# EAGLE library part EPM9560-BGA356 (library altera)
EPM9560 MAX 9000 family
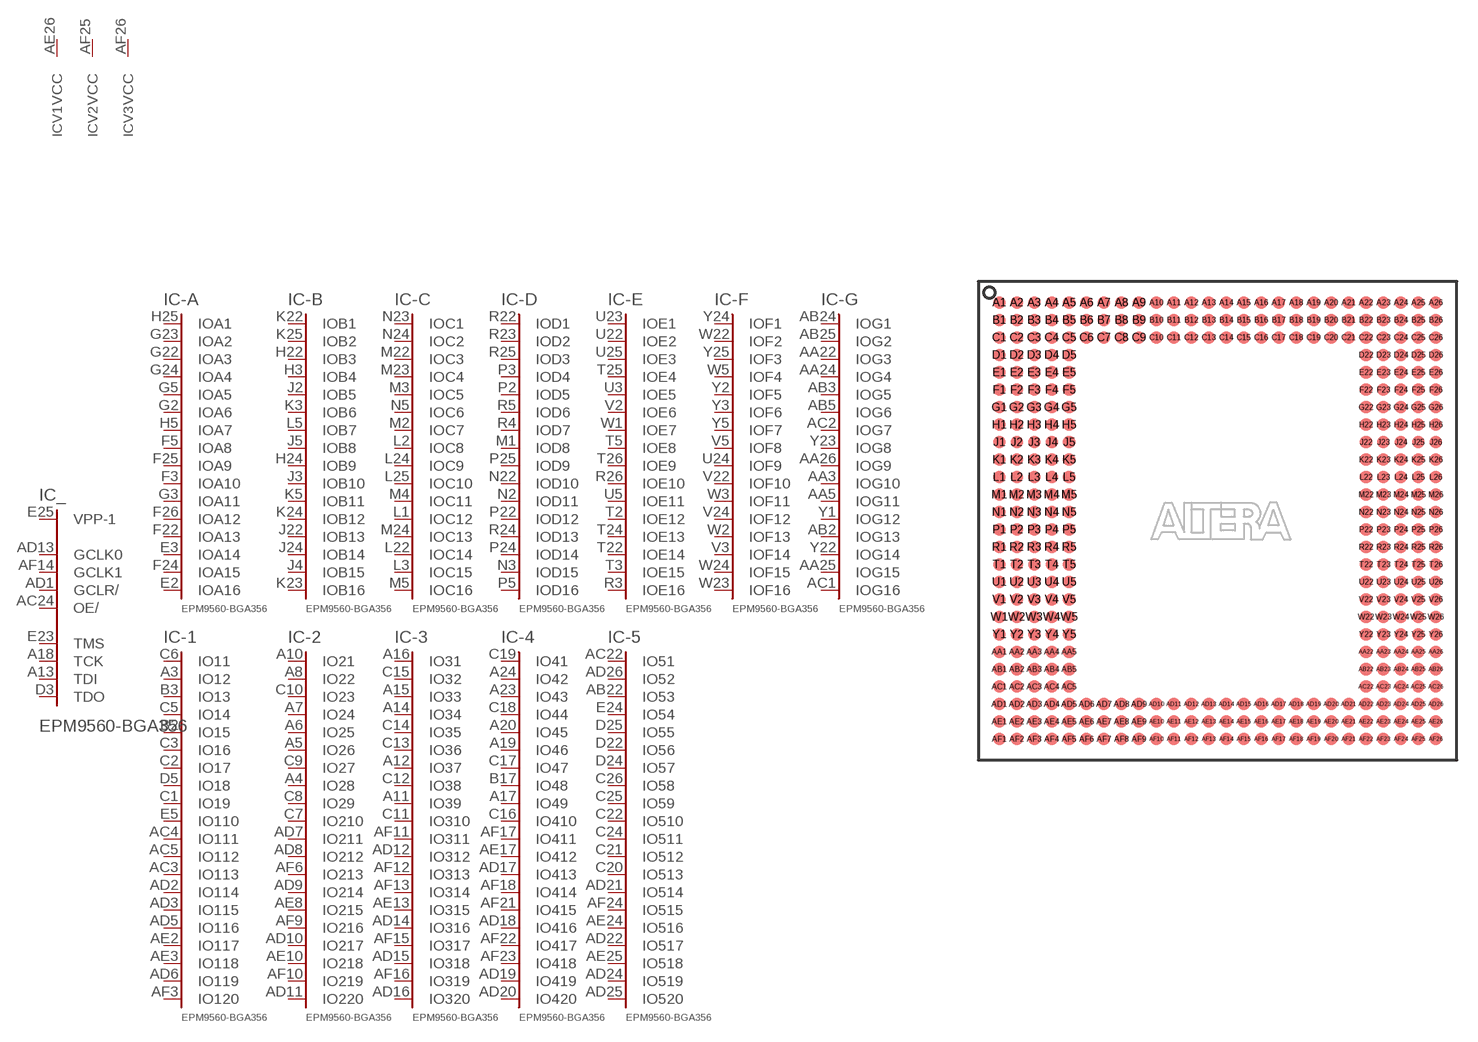
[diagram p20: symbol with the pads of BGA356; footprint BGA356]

Designator prefix IC; gates _=9560C356 -A=A16-0 -B=B16-0 -C=C16-0 -D=D16-0 -E=E16-0 -1=IO120 -2=IO220 -3=IO320 -4=IO420 -5=IO520 -F=F16-0 -G=G16-0 V1=VCCINT V2=VCCINT V3=VCCINT V4=VCCINT V5=VCCINT V6=VCCINT V7=VCCINT V8=VCCINT V9=VCCINT V10=VCCINT V11=VCCINT VO1=VCCIO VO2=VCCIO VO3=VCCIO VO4=VCCIO VO5=VCCIO VO6=VCCIO VO7=VCCIO VO8=VCCIO VO9=VCCIO VO10=VCCIO VO11=VCCIO VO12=VCCIO VO13=VCCIO VO14=VCCIO VO15=VCCIO VO16=VCCIO VO17=VCCIO G1=GND G2=GND G3=GND G4=GND G5=GND G6=GND G7=GND G8=GND G9=GND G10=GND G11=GND G12=GND G13=GND G14=GND G15=GND G16=GND G17=GND G18=GND G19=GND G20=GND G21=GND G22=GND G23=GND G24=GND G25=GND G26=GND G27=GND G28=GND G29=GND G30=GND G31=GND G32=GND G33=GND G34=GND G35=GND G36=GND G37=GND G38=GND G39=GND G40=GND G41=GND NC1=NC NC2=NC NC3=NC NC4=NC NC5=NC NC6=NC NC7=NC NC8=NC NC9=NC NC10=NC NC11=NC NC12=NC NC13=NC NC14=NC NC15=NC NC16=NC NC17=NC NC18=NC NC19=NC NC20=NC NC21=NC NC22=NC NC23=NC NC24=NC NC25=NC NC26=NC NC27=NC NC28=NC NC29=NC NC30=NC NC31=NC NC32=NC NC33=NC NC34=NC NC35=NC NC36=NC NC37=NC NC38=NC NC39=NC NC40=NC NC41=NC NC42=NC NC43=NC NC44=NC NC45=NC NC46=NC NC47=NC NC48=NC NC49=NC NC50=NC NC51=NC NC52=NC NC53=NC NC54=NC NC55=NC NC56=NC NC57=NC NC58=NC NC59=NC NC60=NC NC61=NC NC62=NC NC63=NC NC64=NC NC65=NC NC66=NC

## EPM9560-BGA356 (MPN: EPM9560ABC356-10; OC_FARNELL: unknown; OC_NEWARK: 51R9960)  [BGA356]
A1  VO6:VCCIO  pwr
A2  VO7:VCCIO  pwr
A3  -1:IO12
A4  -2:IO28
A5  -2:IO26
A6  -2:IO25
A7  -2:IO24
A8  -2:IO22
A9  G11:GND  pwr
A10  -2:IO21
A11  -3:IO39
A12  -3:IO37
A13  _:TDI
A14  -3:IO34
A15  -3:IO33
A16  -3:IO31
A17  -4:IO49
A18  _:TCK
A19  -4:IO46
A20  -4:IO45
A21  VO8:VCCIO  pwr
A22  G12:GND  pwr
A23  -4:IO43
A24  -4:IO42
A25  G13:GND  pwr
A26  G14:GND  pwr
AA1  VO1:VCCIO  pwr
AA2  G1:GND  pwr
AA3  -G:IOG10
AA4  NC1:NC  nc
AA5  -G:IOG11
AA22  -G:IOG3
AA23  NC2:NC  nc
AA24  -G:IOG4
AA25  -G:IOG15
AA26  -G:IOG9
AB1  G2:GND  pwr
AB2  -G:IOG13
AB3  -G:IOG5
AB4  NC3:NC  nc
AB5  -G:IOG6
AB22  -5:IO53
AB23  NC4:NC  nc
AB24  -G:IOG1
AB25  -G:IOG2
AB26  G3:GND  pwr
AC1  -G:IOG16
AC2  -G:IOG7
AC3  -1:IO113
AC4  -1:IO111
AC5  -1:IO112
AC22  -5:IO51
AC23  NC5:NC  nc
AC24  _:OE/  in
AC25  VO2:VCCIO  pwr
AC26  G4:GND  pwr
AD1  _:GCLR/  in
AD2  -1:IO114
AD3  -1:IO115
AD4  NC6:NC  nc
AD5  -1:IO116
AD6  -1:IO119
AD7  -2:IO211
AD8  -2:IO212
AD9  -2:IO214
AD10  -2:IO217
AD11  -2:IO220
AD12  -3:IO312
AD13  _:GCLK0  in
AD14  -3:IO316
AD15  -3:IO318
AD16  -3:IO320
AD17  -4:IO413
AD18  -4:IO416
AD19  -4:IO419
AD20  -4:IO420
AD21  -5:IO514
AD22  -5:IO517
AD23  NC7:NC  nc
AD24  -5:IO519
AD25  -5:IO520
AD26  -5:IO52
AE1  G5:GND  pwr
AE2  -1:IO117
AE3  -1:IO118
AE4  NC8:NC  nc
AE5  NC9:NC  nc
AE6  NC10:NC  nc
AE7  NC11:NC  nc
AE8  -2:IO215
AE9  NC12:NC  nc
AE10  -2:IO218
AE11  NC13:NC  nc
AE12  NC14:NC  nc
AE13  -3:IO315
AE14  NC15:NC  nc
AE15  NC16:NC  nc
AE16  NC17:NC  nc
AE17  -4:IO412
AE18  NC18:NC  nc
AE19  NC19:NC  nc
AE20  NC20:NC  nc
AE21  NC21:NC  nc
AE22  NC22:NC  nc
AE23  NC23:NC  nc
AE24  -5:IO516
AE25  -5:IO518
AE26  V1:VCC  pwr
AF1  G6:GND  pwr
AF2  G7:GND  pwr
AF3  -1:IO120
AF4  G8:GND  pwr
AF5  VO3:VCCIO  pwr
AF6  -2:IO213
AF7  G9:GND  pwr
AF8  VO4:VCCIO  pwr
AF9  -2:IO216
AF10  -2:IO219
AF11  -3:IO311
AF12  -3:IO313
AF13  -3:IO314
AF14  _:GCLK1  in
AF15  -3:IO317
AF16  -3:IO319
AF17  -4:IO411
AF18  -4:IO414
AF19  VO5:VCCIO  pwr
AF20  G10:GND  pwr
AF21  -4:IO415
AF22  -4:IO417
AF23  -4:IO418
AF24  -5:IO515
AF25  V2:VCC  pwr
AF26  V3:VCC  pwr
B1  VO9:VCCIO  pwr
B2  -1:IO15
B3  -1:IO13
B4  NC24:NC  nc
B5  NC25:NC  nc
B6  NC26:NC  nc
B7  NC27:NC  nc
B8  NC28:NC  nc
B9  NC29:NC  nc
B10  VO10:VCCIO  pwr
B11  NC30:NC  nc
B12  NC31:NC  nc
B13  NC32:NC  nc
B14  NC33:NC  nc
B15  NC34:NC  nc
B16  NC35:NC  nc
B17  -4:IO48
B18  NC36:NC  nc
B19  NC37:NC  nc
B20  NC38:NC  nc
B21  NC39:NC  nc
B22  NC40:NC  nc
B23  NC41:NC  nc
B24  VO11:VCCIO  pwr
B25  G15:GND  pwr
B26  G16:GND  pwr
C1  -1:IO19
C2  -1:IO17
C3  -1:IO16
C4  NC42:NC  nc
C5  -1:IO14
C6  -1:IO11
C7  -2:IO210
C8  -2:IO29
C9  -2:IO27
C10  -2:IO23
C11  -3:IO310
C12  -3:IO38
C13  -3:IO36
C14  -3:IO35
C15  -3:IO32
C16  -4:IO410
C17  -4:IO47
C18  -4:IO44
C19  -4:IO41
C20  -5:IO513
C21  -5:IO512
C22  -5:IO510
C23  NC43:NC  nc
C24  -5:IO511
C25  -5:IO59
C26  -5:IO58
D1  VO12:VCCIO  pwr
D2  G17:GND  pwr
D3  _:TDO
D4  NC44:NC  nc
D5  -1:IO18
D22  -5:IO56
D23  NC45:NC  nc
D24  -5:IO57
D25  -5:IO55
D26  V4:VCC  pwr
E1  G18:GND  pwr
E2  -A:IOA16
E3  -A:IOA14
E4  NC46:NC  nc
E5  -1:IO110
E22  NC47:NC  nc
E23  _:TMS
E24  -5:IO54
E25  _:VPP-1  in
E26  G19:GND  pwr
F1  V5:VCC  pwr
F2  G20:GND  pwr
F3  -A:IOA10
F4  NC48:NC  nc
F5  -A:IOA8
F22  -A:IOA13
F23  NC49:NC  nc
F24  -A:IOA15
F25  -A:IOA9
F26  -A:IOA12
G1  G21:GND  pwr
G2  -A:IOA6
G3  -A:IOA11
G4  NC50:NC  nc
G5  -A:IOA5
G22  -A:IOA3
G23  -A:IOA2
G24  -A:IOA4
G25  G22:GND  pwr
G26  G23:GND  pwr
H1  V6:VCC  pwr
H2  G24:GND  pwr
H3  -B:IOB4
H4  NC51:NC  nc
H5  -A:IOA7
H22  -B:IOB3
H23  NC52:NC  nc
H24  -B:IOB9
H25  -A:IOA1
H26  VO13:VCCIO  pwr
J1  G25:GND  pwr
J2  -B:IOB5
J3  -B:IOB10
J4  -B:IOB15
J5  -B:IOB8
J22  -B:IOB13
J23  NC53:NC  nc
J24  -B:IOB14
J25  G26:GND  pwr
J26  G27:GND  pwr
K1  VO14:VCCIO  pwr
K2  G28:GND  pwr
K3  -B:IOB6
K4  NC54:NC  nc
K5  -B:IOB11
K22  -B:IOB1
K23  -B:IOB16
K24  -B:IOB12
K25  -B:IOB2
K26  V7:VCC  pwr
L1  -C:IOC12
L2  -C:IOC8
L3  -C:IOC15
L4  NC55:NC  nc
L5  -B:IOB7
L22  -C:IOC14
L23  NC56:NC  nc
L24  -C:IOC9
L25  -C:IOC10
L26  G29:GND  pwr
M1  -D:IOD8
M2  -C:IOC7
M3  -C:IOC5
M4  -C:IOC11
M5  -C:IOC16
M22  -C:IOC3
M23  -C:IOC4
M24  -C:IOC13
M25  VO15:VCCIO  pwr
M26  G30:GND  pwr
N1  G31:GND  pwr
N2  -D:IOD11
N3  -D:IOD15
N4  NC57:NC  nc
N5  -C:IOC6
N22  -D:IOD10
N23  -C:IOC1
N24  -C:IOC2
N25  G32:GND  pwr
N26  V8:VCC  pwr
P1  V9:VCC  pwr
P2  -D:IOD5
P3  -D:IOD4
P4  NC58:NC  nc
P5  -D:IOD16
P22  -D:IOD12
P23  NC59:NC  nc
P24  -D:IOD14
P25  -D:IOD9
P26  G33:GND  pwr
R1  VO16:VCCIO  pwr
R2  G34:GND  pwr
R3  -E:IOE16
R4  -D:IOD7
R5  -D:IOD6
R22  -D:IOD1
R23  -D:IOD2
R24  -D:IOD13
R25  -D:IOD3
R26  -E:IOE10
T1  G35:GND  pwr
T2  -E:IOE12
T3  -E:IOE15
T4  NC60:NC  nc
T5  -E:IOE8
T22  -E:IOE14
T23  NC61:NC  nc
T24  -E:IOE13
T25  -E:IOE4
T26  -E:IOE9
U1  V10:VCC  pwr
U2  G36:GND  pwr
U3  -E:IOE5
U4  NC62:NC  nc
U5  -E:IOE11
U22  -E:IOE2
U23  -E:IOE1
U24  -F:IOF9
U25  -E:IOE3
U26  G37:GND  pwr
V1  G38:GND  pwr
V2  -E:IOE6
V3  -F:IOF14
V4  NC63:NC  nc
V5  -F:IOF8
V22  -F:IOF10
V23  NC64:NC  nc
V24  -F:IOF12
V25  G39:GND  pwr
V26  VO17:VCCIO  pwr
W1  -E:IOE7
W2  -F:IOF13
W3  -F:IOF11
W4  NC65:NC  nc
W5  -F:IOF4
W22  -F:IOF2
W23  -F:IOF16
W24  -F:IOF15
W25  G40:GND  pwr
W26  V11:VCC  pwr
Y1  -G:IOG12
Y2  -F:IOF5
Y3  -F:IOF6
Y4  NC66:NC  nc
Y5  -F:IOF7
Y22  -G:IOG14
Y23  -G:IOG8
Y24  -F:IOF1
Y25  -F:IOF3
Y26  G41:GND  pwr

## Footprint BGA356 (pad centres in mm)
Ball Grid Array
smd 0.9 x 0.9: A1 -15.875,15.875; A2 -14.605,15.875; A3 -13.335,15.875; A4 -12.065,15.875; A5 -10.795,15.875; A6 -9.525,15.875; A7 -8.255,15.875; A8 -6.985,15.875; A9 -5.715,15.875; A10 -4.445,15.875; A11 -3.175,15.875; A12 -1.905,15.875; A13 -0.635,15.875; A14 0.635,15.875; A15 1.905,15.875; A16 3.175,15.875; A17 4.445,15.875; A18 5.715,15.875; A19 6.985,15.875; A20 8.255,15.875; A21 9.525,15.875; A22 10.795,15.875; A23 12.065,15.875; A24 13.335,15.875; A25 14.605,15.875; A26 15.875,15.875; AA1 -15.875,-9.525; AA2 -14.605,-9.525; AA3 -13.335,-9.525; AA4 -12.065,-9.525; AA5 -10.795,-9.525; AA22 10.795,-9.525; AA23 12.065,-9.525; AA24 13.335,-9.525; AA25 14.605,-9.525; AA26 15.875,-9.525; AB1 -15.875,-10.795; AB2 -14.605,-10.795; AB3 -13.335,-10.795; AB4 -12.065,-10.795; AB5 -10.795,-10.795; AB22 10.795,-10.795; AB23 12.065,-10.795; AB24 13.335,-10.795; AB25 14.605,-10.795; AB26 15.875,-10.795; AC1 -15.875,-12.065; AC2 -14.605,-12.065; AC3 -13.335,-12.065; AC4 -12.065,-12.065; AC5 -10.795,-12.065; AC22 10.795,-12.065; AC23 12.065,-12.065; AC24 13.335,-12.065; AC25 14.605,-12.065; AC26 15.875,-12.065; AD1 -15.875,-13.335; AD2 -14.605,-13.335; AD3 -13.335,-13.335; AD4 -12.065,-13.335; AD5 -10.795,-13.335; AD6 -9.525,-13.335; AD7 -8.255,-13.335; AD8 -6.985,-13.335; AD9 -5.715,-13.335; AD10 -4.445,-13.335; AD11 -3.175,-13.335; AD12 -1.905,-13.335; AD13 -0.635,-13.335; AD14 0.635,-13.335; AD15 1.905,-13.335; AD16 3.175,-13.335; AD17 4.445,-13.335; AD18 5.715,-13.335; AD19 6.985,-13.335; AD20 8.255,-13.335; AD21 9.525,-13.335; AD22 10.795,-13.335; AD23 12.065,-13.335; AD24 13.335,-13.335; AD25 14.605,-13.335; AD26 15.875,-13.335; AE1 -15.875,-14.605; AE2 -14.605,-14.605; AE3 -13.335,-14.605; AE4 -12.065,-14.605; AE5 -10.795,-14.605; AE6 -9.525,-14.605; AE7 -8.255,-14.605; AE8 -6.985,-14.605; AE9 -5.715,-14.605; AE10 -4.445,-14.605; AE11 -3.175,-14.605; AE12 -1.905,-14.605; AE13 -0.635,-14.605; AE14 0.635,-14.605; AE15 1.905,-14.605; AE16 3.175,-14.605; AE17 4.445,-14.605; AE18 5.715,-14.605; AE19 6.985,-14.605; AE20 8.255,-14.605; AE21 9.525,-14.605; AE22 10.795,-14.605; AE23 12.065,-14.605; AE24 13.335,-14.605; AE25 14.605,-14.605; AE26 15.875,-14.605; AF1 -15.875,-15.875; AF2 -14.605,-15.875; AF3 -13.335,-15.875; AF4 -12.065,-15.875; AF5 -10.795,-15.875; AF6 -9.525,-15.875; AF7 -8.255,-15.875; AF8 -6.985,-15.875; AF9 -5.715,-15.875; AF10 -4.445,-15.875; AF11 -3.175,-15.875; AF12 -1.905,-15.875; AF13 -0.635,-15.875; AF14 0.635,-15.875; AF15 1.905,-15.875; AF16 3.175,-15.875; AF17 4.445,-15.875; AF18 5.715,-15.875; AF19 6.985,-15.875; AF20 8.255,-15.875; AF21 9.525,-15.875; AF22 10.795,-15.875; AF23 12.065,-15.875; AF24 13.335,-15.875; AF25 14.605,-15.875; AF26 15.875,-15.875; B1 -15.875,14.605; B2 -14.605,14.605; B3 -13.335,14.605; B4 -12.065,14.605; B5 -10.795,14.605; B6 -9.525,14.605; B7 -8.255,14.605; B8 -6.985,14.605; B9 -5.715,14.605; B10 -4.445,14.605; B11 -3.175,14.605; B12 -1.905,14.605; B13 -0.635,14.605; B14 0.635,14.605; B15 1.905,14.605; B16 3.175,14.605; B17 4.445,14.605; B18 5.715,14.605; B19 6.985,14.605; B20 8.255,14.605; B21 9.525,14.605; B22 10.795,14.605; B23 12.065,14.605; B24 13.335,14.605; B25 14.605,14.605; B26 15.875,14.605; C1 -15.875,13.335; C2 -14.605,13.335; C3 -13.335,13.335; C4 -12.065,13.335; C5 -10.795,13.335; C6 -9.525,13.335; C7 -8.255,13.335; C8 -6.985,13.335; C9 -5.715,13.335; C10 -4.445,13.335; C11 -3.175,13.335; C12 -1.905,13.335; C13 -0.635,13.335; C14 0.635,13.335; C15 1.905,13.335; C16 3.175,13.335; C17 4.445,13.335; C18 5.715,13.335; C19 6.985,13.335; C20 8.255,13.335; C21 9.525,13.335; C22 10.795,13.335; C23 12.065,13.335; C24 13.335,13.335; C25 14.605,13.335; C26 15.875,13.335; D1 -15.875,12.065; D2 -14.605,12.065; D3 -13.335,12.065; D4 -12.065,12.065; D5 -10.795,12.065; D22 10.795,12.065; D23 12.065,12.065; D24 13.335,12.065; D25 14.605,12.065; D26 15.875,12.065; E1 -15.875,10.795; E2 -14.605,10.795; E3 -13.335,10.795; E4 -12.065,10.795; E5 -10.795,10.795; E22 10.795,10.795; E23 12.065,10.795; E24 13.335,10.795; E25 14.605,10.795; E26 15.875,10.795; F1 -15.875,9.525; F2 -14.605,9.525; F3 -13.335,9.525; F4 -12.065,9.525; F5 -10.795,9.525; F22 10.795,9.525; F23 12.065,9.525; F24 13.335,9.525; F25 14.605,9.525; F26 15.875,9.525; G1 -15.875,8.255; G2 -14.605,8.255; G3 -13.335,8.255; G4 -12.065,8.255; G5 -10.795,8.255; G22 10.795,8.255; G23 12.065,8.255; G24 13.335,8.255; G25 14.605,8.255; G26 15.875,8.255; H1 -15.875,6.985; H2 -14.605,6.985; H3 -13.335,6.985; H4 -12.065,6.985; H5 -10.795,6.985; H22 10.795,6.985; H23 12.065,6.985; H24 13.335,6.985; H25 14.605,6.985; H26 15.875,6.985; J1 -15.875,5.715; J2 -14.605,5.715; J3 -13.335,5.715; J4 -12.065,5.715; J5 -10.795,5.715; J22 10.795,5.715; J23 12.065,5.715; J24 13.335,5.715; J25 14.605,5.715; J26 15.875,5.715; K1 -15.875,4.445; K2 -14.605,4.445; K3 -13.335,4.445; K4 -12.065,4.445; K5 -10.795,4.445; K22 10.795,4.445; K23 12.065,4.445; K24 13.335,4.445; K25 14.605,4.445; K26 15.875,4.445; L1 -15.875,3.175; L2 -14.605,3.175; L3 -13.335,3.175; L4 -12.065,3.175; L5 -10.795,3.175; L22 10.795,3.175; L23 12.065,3.175; L24 13.335,3.175; L25 14.605,3.175; L26 15.875,3.175; M1 -15.875,1.905; M2 -14.605,1.905; M3 -13.335,1.905; M4 -12.065,1.905; M5 -10.795,1.905; M22 10.795,1.905; M23 12.065,1.905; M24 13.335,1.905; M25 14.605,1.905; M26 15.875,1.905; N1 -15.875,0.635; N2 -14.605,0.635; N3 -13.335,0.635; N4 -12.065,0.635; N5 -10.795,0.635; N22 10.795,0.635; N23 12.065,0.635; N24 13.335,0.635; N25 14.605,0.635; N26 15.875,0.635; P1 -15.875,-0.635; P2 -14.605,-0.635; P3 -13.335,-0.635; P4 -12.065,-0.635; P5 -10.795,-0.635; P22 10.795,-0.635; P23 12.065,-0.635; P24 13.335,-0.635; P25 14.605,-0.635; P26 15.875,-0.635; R1 -15.875,-1.905; R2 -14.605,-1.905; R3 -13.335,-1.905; R4 -12.065,-1.905; R5 -10.795,-1.905; R22 10.795,-1.905; R23 12.065,-1.905; R24 13.335,-1.905; R25 14.605,-1.905; R26 15.875,-1.905; T1 -15.875,-3.175; T2 -14.605,-3.175; T3 -13.335,-3.175; T4 -12.065,-3.175; T5 -10.795,-3.175; T22 10.795,-3.175; T23 12.065,-3.175; T24 13.335,-3.175; T25 14.605,-3.175; T26 15.875,-3.175; U1 -15.875,-4.445; U2 -14.605,-4.445; U3 -13.335,-4.445; U4 -12.065,-4.445; U5 -10.795,-4.445; U22 10.795,-4.445; U23 12.065,-4.445; U24 13.335,-4.445; U25 14.605,-4.445; U26 15.875,-4.445; V1 -15.875,-5.715; V2 -14.605,-5.715; V3 -13.335,-5.715; V4 -12.065,-5.715; V5 -10.795,-5.715; V22 10.795,-5.715; V23 12.065,-5.715; V24 13.335,-5.715; V25 14.605,-5.715; V26 15.875,-5.715; W1 -15.875,-6.985; W2 -14.605,-6.985; W3 -13.335,-6.985; W4 -12.065,-6.985; W5 -10.795,-6.985; W22 10.795,-6.985; W23 12.065,-6.985; W24 13.335,-6.985; W25 14.605,-6.985; W26 15.875,-6.985; Y1 -15.875,-8.255; Y2 -14.605,-8.255; Y3 -13.335,-8.255; Y4 -12.065,-8.255; Y5 -10.795,-8.255; Y22 10.795,-8.255; Y23 12.065,-8.255; Y24 13.335,-8.255; Y25 14.605,-8.255; Y26 15.875,-8.255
